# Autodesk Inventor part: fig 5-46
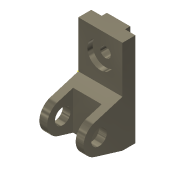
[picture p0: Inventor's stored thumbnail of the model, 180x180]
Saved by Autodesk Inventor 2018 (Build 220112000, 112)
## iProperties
Shininess: 65.0
Angle Display Precision: 2
Document Length Units: 11269
Document Angle Units: 11279
Document Time Units: 11290
Document Mass Units: 11283
Document Length Units Precision: 3
Document Angle Units Precision: 2
Created: 2001-11
Part Number: fig 5-46
Document SubType Name: Modeling
Designer: Renu Muthoo
Density: 1 g/cm^3
Material: Generic
Appearance: Metal-Titanium (Polished)
Density: 0.0
Volumn: 0.0
Area: 0.0
PropertySet Name: Model Information
Control State: 0
Master: False
Checked Out: False
Author: Renu Muthoo
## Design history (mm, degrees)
node "Sketch1"
sketch "Sketch2"
  geometry: L1 (33.257, 104.664)-(33.257, -75.336); L2 (33.257, -75.336)-(8.257, -75.336); L3 (8.257, -75.336)-(-45.451, -59.045); L4 (-45.451, -1.628)-(8.257, 14.664); L5 (8.257, 14.664)-(8.257, 104.664); L6 (8.257, 104.664)-(33.257, 104.664); C1 r 15 at (-36.743, -30.336); A1 r 30 centre (-36.743, -30.336) between (-45.451, -1.628) and (-45.451, -59.045)
  constraints: 12 end point, 2 centre point, 2 equal length, 2 parallel, 2 point on circle, 2 tangent, 1 coincident, 1 perpendicular, 1 vertical
  dimensions: "d0" = 180 distance of L1.start L1.end; "d1" = 30 radius of A1; "d2" = 25 distance of L5.end L1.start; "d3" = 45 distance from line of L2 A1.centre; "d4" = 70 distance from line of L1 A1.centre; "d5" = 30 diameter of C1
extrude "Extrusion1" new body sketch "Sketch2" distance "d6" = 85; taper "d7" = 0 deg
workplane "Work Plane1"
sketch "Sketch3"
  geometry: L1 (15, 62.364)-(70, 62.364); L2 (70, 62.364)-(70, -52.386); L3 (70, -52.386)-(15, -52.386); L4 (15, -52.386)-(15, 62.364); L5 (0, -45)-(0, -28.708) reference
  constraints: 8 end point, 2 parallel, 1 horizontal, 1 perpendicular
  dimensions: "d8" = 55 distance of L1.start L1.end; "d9" = 15 distance between parallel lines of L5 L4
extrude "Extrusion2" cut sketch "Sketch3" distance "d10" = 50; taper "d11" = 0 deg
sketch "Sketch4"
  geometry: L1 (0, 25)-(85, 25) reference; L2 (0, 0)-(0, 25) reference; L3 (20, 25)-(65, 25); L4 (65, 25)-(65, 35); L5 (65, 35)-(20, 35); L6 (20, 35)-(20, 25)
  constraints: 8 end point, 2 parallel, 1 horizontal, 1 perpendicular, 1 point on line
  dimensions: "d12" = 45 distance of L4.end L5.end; "d13" = 10 distance of L3.end L4.end; "d14" = 20 distance between parallel lines of L2 L6
extrude "Extrusion3" join sketch "Sketch4" stored distance "d15" = 50; taper "d16" = 0 deg
sketch "Sketch5"
  geometry: L1 (85, 0)-(85, 90) reference; L2 (0, 90)-(85, 90) reference; 1 further point
  dimensions: "d17" = 42 distance from line of L2 point (42.5, 48); "d18" = 42.5 distance from line of L1 point (42.5, 48)
hole "Hole1" sketch "Sketch5" at (42.5, 48) diameter "d19" = 20; stored, may be unused: countersink angle "d23" = 82 deg, drill point angle "d25" = 118 deg; dims "d20" = 6, "d21" = 50, "d22" = 10, "d24" = 8
workpoint "Work Point5"
body "Solid1"
